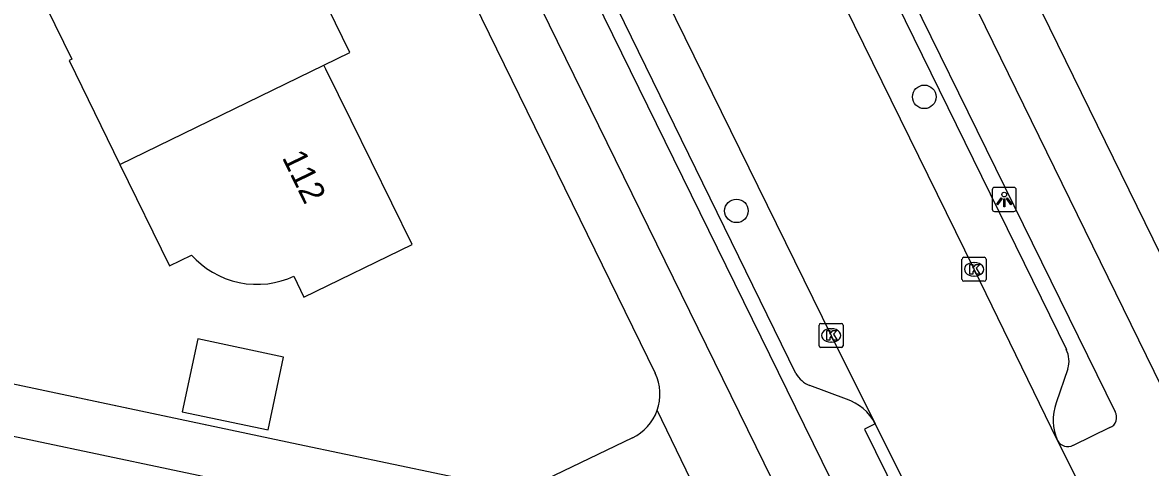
# Model space of a CAD drawing. Extents: x 160457 to 162082, y 388340 to 389736.
# Drawn here: x 160864.94 to 160911.77, y 389001.22 to 389019.72 of the extents above; entities that cross this region are included whole.
import ezdxf

# ---------------------------------------------------------------- set-up
doc = ezdxf.new("R2010")
doc.units = 0
for name, color, linetype in [('IMGEO_Boom', 7, 'Continuous'), ('IMGEO_Fietspad_gesloten', 7, 'Continuous'), ('IMGEO_Kolk', 7, 'Continuous'), ('IMGEO_Lichtpunt', 7, 'Continuous'), ('IMGEO_Muur', 7, 'Continuous'), ('IMGEO_Pand', 7, 'Continuous'), ('IMGEO_Pand_nummerreeks', 7, 'Continuous'), ('IMGEO_Parkeervlak_open', 7, 'Continuous'), ('IMGEO_Rijbaan_lokaal_gesloten', 7, 'Continuous'), ('IMGEO_Verkeerseiland_open', 7, 'Continuous'), ('IMGEO_Voetpad_open', 7, 'Continuous')]:
    doc.layers.add(name, color=color, linetype=linetype)

msp = doc.modelspace()

# ---------------------------------------------------------------- linework, layer by layer
at = {"layer": 'IMGEO_Boom'}
for centre in [(160902.38, 389016.633), (160894.579, 389011.892)]:
    msp.add_circle(centre, 0.489, dxfattribs=at)
at = {"layer": 'IMGEO_Fietspad_gesloten'}
for points in [[(160865.149, 389063.924), (160866.884, 389060.338), (160896.406, 389000), (160929.271, 388932.792), (160931.346, 388928.541)], [(160947.207, 388933.03), (160943.921, 388939.826), (160914.477, 389000), (160885.175, 389059.974)], [(160896.532, 389031.633), (160910.3, 389003.541)], [(160910.338, 388976.581), (160898.863, 389000), (160885.472, 389027.328)], [(160910.078, 389002.878), (160908.565, 389002.143)]]:
    msp.add_lwpolyline(points, dxfattribs=at)
for centre, radius, start, end in [((160909.92, 389003.3), 0.45, 290.5547, 32.4199), ((160908.342, 389002.574), 0.485, 208.379, 297.4156)]:
    msp.add_arc(centre, radius, start, end, dxfattribs=at)
at = {"layer": 'IMGEO_Kolk'}
for p, q in [((160903.945, 389009.037), (160903.945, 389009.889)), ((160904.02, 389009.963), (160904.872, 389009.963)), ((160904.433, 389009.743), (160904.458, 389009.743)), ((160904.946, 389009.889), (160904.946, 389009.037)), ((160904.456, 389009.183), (160904.431, 389009.183)), ((160904.872, 389008.963), (160904.02, 389008.963)), ((160898.011, 389006.287), (160898.011, 389007.139)), ((160898.086, 389007.213), (160898.938, 389007.213)), ((160898.499, 389006.993), (160898.524, 389006.993)), ((160899.012, 389007.139), (160899.012, 389006.287)), ((160898.522, 389006.433), (160898.497, 389006.433)), ((160898.938, 389006.213), (160898.086, 389006.213))]:
    msp.add_line(p, q, dxfattribs=at)
for points in [[(160903.945, 389009.037), (160903.945, 389009.889)], [(160904.02, 389009.963), (160904.872, 389009.963)], [(160904.266, 389009.663), (160904.389, 389009.663), (160904.389, 389009.512), (160904.519, 389009.663), (160904.683, 389009.663), (160904.537, 389009.512), (160904.69, 389009.263), (160904.538, 389009.263), (160904.453, 389009.427), (160904.389, 389009.36), (160904.389, 389009.263), (160904.266, 389009.263), (160904.266, 389009.663)], [(160904.946, 389009.889), (160904.946, 389009.037)], [(160904.872, 389008.963), (160904.02, 389008.963)], [(160898.011, 389006.287), (160898.011, 389007.139)], [(160898.086, 389007.213), (160898.938, 389007.213)], [(160898.332, 389006.913), (160898.455, 389006.913), (160898.455, 389006.762), (160898.585, 389006.913), (160898.749, 389006.913), (160898.603, 389006.762), (160898.756, 389006.513), (160898.604, 389006.513), (160898.519, 389006.677), (160898.455, 389006.61), (160898.455, 389006.513), (160898.332, 389006.513), (160898.332, 389006.913)], [(160899.012, 389007.139), (160899.012, 389006.287)], [(160898.938, 389006.213), (160898.086, 389006.213)]]:
    msp.add_lwpolyline(points, dxfattribs=at)
for centre, start, end in [((160904.022, 389009.887), 91.552, 178.448), ((160904.022, 389009.887), 91.552, 178.448), ((160904.87, 389009.887), 1.552, 88.448), ((160904.87, 389009.887), 1.552, 88.448), ((160904.022, 389009.039), 181.552, 268.448), ((160904.022, 389009.039), 181.552, 268.448), ((160904.87, 389009.039), 271.552, 358.448), ((160904.87, 389009.039), 271.552, 358.448), ((160898.088, 389007.137), 91.552, 178.448), ((160898.088, 389007.137), 91.552, 178.448), ((160898.936, 389007.137), 1.552, 88.448), ((160898.936, 389007.137), 1.552, 88.448), ((160898.088, 389006.289), 181.552, 268.448), ((160898.088, 389006.289), 181.552, 268.448), ((160898.936, 389006.289), 271.552, 358.448), ((160898.936, 389006.289), 271.552, 358.448)]:
    msp.add_arc(centre, 0.0765, start, end, dxfattribs=at)
for centre, major_axis, ratio, start_param, end_param in [((160904.432, 389009.463), (-0.387, 0.002), 0.722429, 4.712389, 7.853982), ((160904.457, 389009.463), (-0.39, 0.002), 0.717154, 1.570796, 4.712389), ((160898.498, 389006.713), (-0.387, 0.002), 0.722429, 4.712389, 7.853982), ((160898.523, 389006.713), (-0.39, 0.002), 0.717154, 1.570796, 4.712389)]:
    msp.add_ellipse(centre, major_axis=major_axis, ratio=ratio, start_param=start_param, end_param=end_param, dxfattribs=at)
at = {"layer": 'IMGEO_Lichtpunt'}
for p, q in [((160906.103, 389012.867), (160905.295, 389012.867)), ((160906.103, 389012.867), (160905.295, 389012.867)), ((160905.201, 389012.772), (160905.201, 389011.965)), ((160905.201, 389012.772), (160905.201, 389011.965)), ((160906.197, 389011.965), (160906.197, 389012.772)), ((160906.197, 389011.965), (160906.197, 389012.772)), ((160905.295, 389011.871), (160906.103, 389011.871)), ((160905.295, 389011.871), (160906.103, 389011.871))]:
    msp.add_line(p, q, dxfattribs=at)
for points in [[(160905.575, 389012.436), (160905.614, 389012.408), (160905.426, 389012.146), (160905.388, 389012.173), (160905.575, 389012.436)], [(160905.787, 389012.408), (160905.825, 389012.435), (160906.012, 389012.173), (160905.973, 389012.145), (160905.787, 389012.408)], [(160905.677, 389012.388), (160905.724, 389012.388), (160905.724, 389012.066), (160905.677, 389012.066), (160905.677, 389012.388)]]:
    msp.add_lwpolyline(points, dxfattribs=at)
msp.add_circle((160905.7, 389012.57), 0.0994, dxfattribs=at)
for centre, start, end in [((160905.295, 389012.772), 90, 180), ((160905.295, 389012.772), 90, 180), ((160906.103, 389012.772), 0, 90), ((160906.103, 389012.772), 0, 90), ((160905.295, 389011.965), 180, 270), ((160905.295, 389011.965), 180, 270), ((160906.103, 389011.965), 270, 0), ((160906.103, 389011.965), 270, 360)]:
    msp.add_arc(centre, 0.0946, start, end, dxfattribs=at)
at = {"layer": 'IMGEO_Muur'}
msp.add_lwpolyline([(160876.381, 389002.172), (160854.217, 389006.879)], dxfattribs=at)
at = {"layer": 'IMGEO_Pand'}
for points in [[(160877.449, 389017.947), (160878.529, 389018.474), (160876.42, 389022.798), (160875.341, 389022.272), (160874.462, 389024.074), (160873.583, 389025.877), (160873.508, 389026.031)], [(160865.037, 389021.906), (160865.111, 389021.752), (160865.219, 389021.805), (160866.977, 389018.201), (160866.869, 389018.148), (160868.982, 389013.816)], [(160868.982, 389013.816), (160871.035, 389009.607), (160871.95, 389010.053), (160872.141, 389009.856), (160872.35, 389009.67), (160872.578, 389009.497), (160872.822, 389009.34), (160873.082, 389009.201), (160873.355, 389009.083), (160873.638, 389008.987), (160873.929, 389008.914), (160874.226, 389008.865), (160874.524, 389008.841), (160874.821, 389008.841), (160875.114, 389008.865), (160875.401, 389008.912), (160875.678, 389008.98), (160875.945, 389009.068), (160876.198, 389009.173), (160876.618, 389008.31), (160881.113, 389010.494), (160878.58, 389015.648), (160877.526, 389017.791), (160877.449, 389017.947)], [(160868.982, 389013.816), (160877.449, 389017.947)], [(160875.776, 389005.816), (160872.214, 389006.574), (160871.569, 389003.542), (160875.131, 389002.784), (160875.776, 389005.816)]]:
    msp.add_lwpolyline(points, dxfattribs=at)
at = {"layer": 'IMGEO_Parkeervlak_open'}
for points in [[(160895.953, 389031.324), (160908.278, 389006.124)], [(160897.052, 389005.136), (160886.073, 389027.642)], [(160908.343, 389005.328), (160907.861, 389003.906)], [(160899.145, 389004.065), (160897.623, 389004.633)]]:
    msp.add_lwpolyline(points, dxfattribs=at)
for centre, radius, start, end in [((160907.313, 389005.645), 1.077, 342.9135, 26.4231), ((160898.026, 389005.666), 1.109, 208.5584, 248.6873), ((160898.486, 389002.083), 2.088, 27.2942, 71.6136), ((160909.704, 389003.187), 1.978, 158.6973, 205.2602)]:
    msp.add_arc(centre, radius, start, end, dxfattribs=at)
at = {"layer": 'IMGEO_Rijbaan_lokaal_gesloten'}
for points in [[(160907.915, 389002.343), (160904.445, 389009.463), (160894.513, 389029.747), (160887.316, 389044.404), (160880.913, 389057.526)], [(160876.244, 389052.308), (160881.582, 389041.416), (160888.628, 389026.872), (160898.512, 389006.713), (160900.342, 389003.041)], [(160900.342, 389003.041), (160901.842, 389000), (160906.66, 388990.235)], [(160907.915, 389002.343), (160909.071, 389000), (160910.509, 388997.087)]]:
    msp.add_lwpolyline(points, dxfattribs=at)
at = {"layer": 'IMGEO_Verkeerseiland_open'}
msp.add_lwpolyline([(160900.342, 389003.041), (160899.894, 389002.82), (160901.285, 389000), (160906.212, 388990.014), (160906.66, 388990.235)], dxfattribs=at)
at = {"layer": 'IMGEO_Voetpad_open'}
for points in [[(160862.667, 389063.549), (160891.208, 389005.138)], [(160915.841, 389002.618), (160898.678, 389037.727), (160898.662, 389037.759)], [(160884.301, 389000.512), (160876.381, 389002.172), (160855.333, 389006.643)], [(160854.443, 389004.661), (160876.487, 389000), (160887.539, 388997.663)], [(160895.886, 388994.089), (160891.29, 389003.601)], [(160890.263, 389002.455), (160886.658, 389000.725)]]:
    msp.add_lwpolyline(points, dxfattribs=at)
for centre, radius, start, end in [((160889.396, 389004.271), 2.009, 340.5318, 25.5759), ((160889.389, 389004.272), 2.016, 295.699, 340.5702)]:
    msp.add_arc(centre, radius, start, end, dxfattribs=at)

# ---------------------------------------------------------------- texts
at = {"layer": 'IMGEO_Pand_nummerreeks'}
msp.add_text('112', height=1, rotation=296.035, dxfattribs=at).set_placement((160875.695, 389014.115))

doc.saveas('drawing.dxf')
